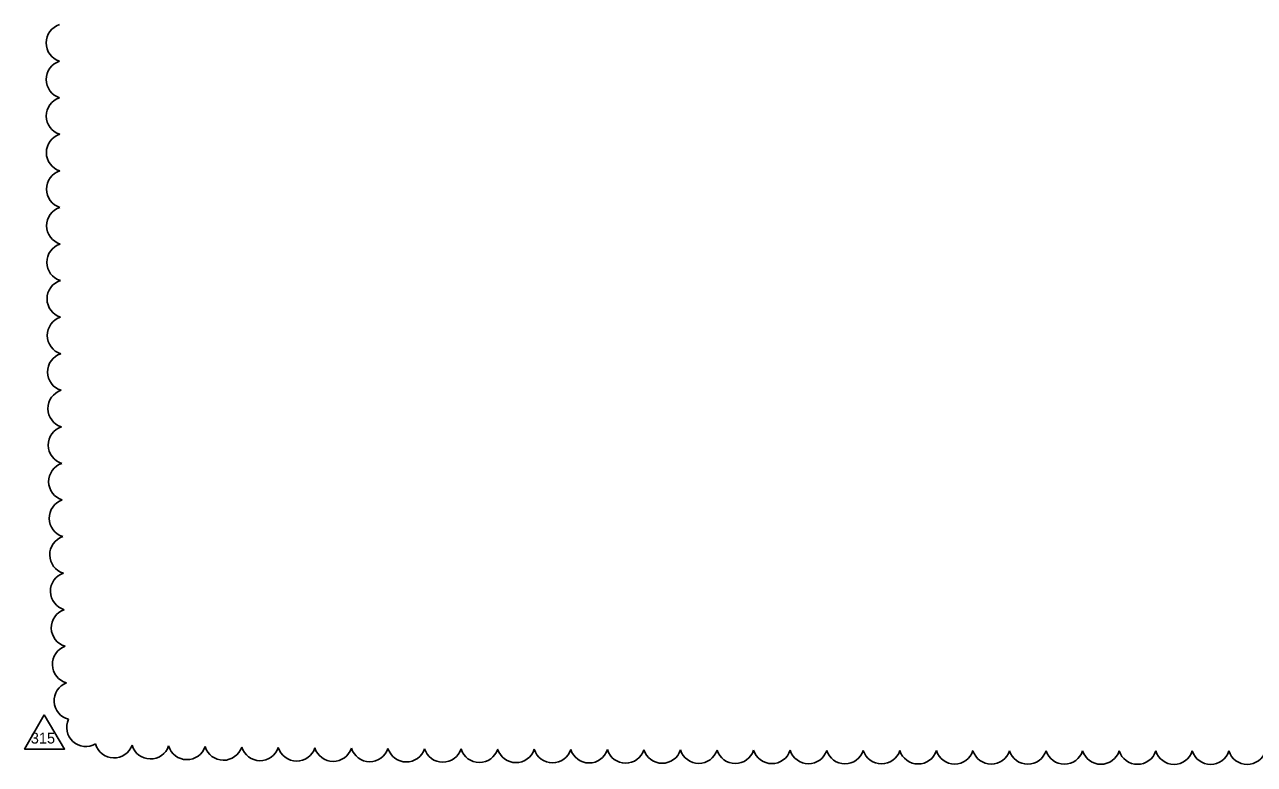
# Model space of a CAD drawing. Extents: x -811.2 to -767.6, y -2295.2 to -2235.1.
# Drawn here: x -783.8 to -777.02, y -2269.67 to -2265.59 of the extents above; entities that cross this region are included whole.
import ezdxf

# ---------------------------------------------------------------- set-up
doc = ezdxf.new("R2010")
doc.units = 0
doc.layers.add('Cloud_dp', color=7, linetype='Continuous')

msp = doc.modelspace()

# ---------------------------------------------------------------- linework, layer by layer
at = {"layer": 'Cloud_dp'}
msp.add_lwpolyline([(-783.6889, -2269.3954), (-783.7966, -2269.5835), (-783.576, -2269.5835)], close=True, dxfattribs=at)
for centre, start, end in [((-783.5723, -2265.6917), 107.59852, 252.59852), ((-783.5719, -2265.8932), 107.62468, 252.62468), ((-783.5714, -2266.0947), 107.65309, 252.65309), ((-783.5708, -2266.2963), 107.68411, 252.68411), ((-783.5701, -2266.4978), 107.71817, 252.71817), ((-783.5693, -2266.6993), 107.75578, 252.75578), ((-783.5683, -2266.9009), 107.79762, 252.79762), ((-783.5672, -2267.1024), 107.84454, 252.84454), ((-783.5659, -2267.3039), 107.89767, 252.89767), ((-783.5644, -2267.5054), 107.95851, 252.95851), ((-783.5626, -2267.7069), 108.02912, 253.02912), ((-783.5606, -2267.9084), 108.11243, 253.11243), ((-783.5583, -2268.1099), 108.21279, 253.21279), ((-783.5556, -2268.3113), 108.33694, 253.33694), ((-783.5523, -2268.5128), 108.49611, 253.49611), ((-783.5485, -2268.7142), 108.71068, 253.71068), ((-783.5437, -2268.9155), 109.02298, 254.02298), ((-783.5374, -2269.1166), 109.54201, 254.54201), ((-783.5282, -2269.3173), 110.71007, 255.71007), ((-783.4585, -2269.4643), 155.06518, 300.06518), ((-783.3038, -2269.5272), 195.62937, 340.62937), ((-783.1027, -2269.5327), 196.26473, 341.26473), ((-782.9013, -2269.5365), 196.54985, 341.54985), ((-782.6999, -2269.5396), 196.72204, 341.72204), ((-782.4984, -2269.5421), 196.84059, 341.84059), ((-782.2969, -2269.5443), 196.92865, 341.92865), ((-782.0954, -2269.5461), 196.99739, 341.99739), ((-781.8939, -2269.5478), 197.053, 342.053), ((-781.6924, -2269.5493), 197.09919, 342.09919), ((-781.4909, -2269.5506), 197.13834, 342.13834), ((-781.2893, -2269.5519), 197.17209, 342.17209), ((-781.0878, -2269.553), 197.20158, 342.20158), ((-780.8863, -2269.554), 197.22762, 342.22762), ((-780.6847, -2269.5549), 197.25085, 342.25085), ((-780.4832, -2269.5557), 197.27174, 342.27174), ((-780.2817, -2269.5565), 197.29065, 342.29065), ((-780.0801, -2269.5572), 197.30788, 342.30788), ((-779.8786, -2269.5578), 197.32367, 342.32367), ((-779.6771, -2269.5584), 197.3382, 342.3382), ((-779.4755, -2269.559), 197.35163, 342.35163), ((-779.274, -2269.5595), 197.3641, 342.3641), ((-779.0724, -2269.5599), 197.37571, 342.37571), ((-778.8709, -2269.5604), 197.38657, 342.38657), ((-778.6693, -2269.5607), 197.39674, 342.39674), ((-778.4678, -2269.5611), 197.40629, 342.40629), ((-778.2663, -2269.5614), 197.4153, 342.4153), ((-778.0647, -2269.5617), 197.4238, 342.4238), ((-777.8632, -2269.5619), 197.43184, 342.43184), ((-777.6616, -2269.5622), 197.43947, 342.43947), ((-777.4601, -2269.5624), 197.44671, 342.44671), ((-777.2585, -2269.5625), 197.4536, 342.4536), ((-777.057, -2269.5627), 197.46017, 342.46017)]:
    msp.add_arc(centre, 0.1057, start, end, dxfattribs=at)

# ---------------------------------------------------------------- texts
msp.add_text('315', height=0.05998, rotation=0, dxfattribs=at).set_placement((-783.7625, -2269.5534))

doc.saveas('drawing.dxf')
